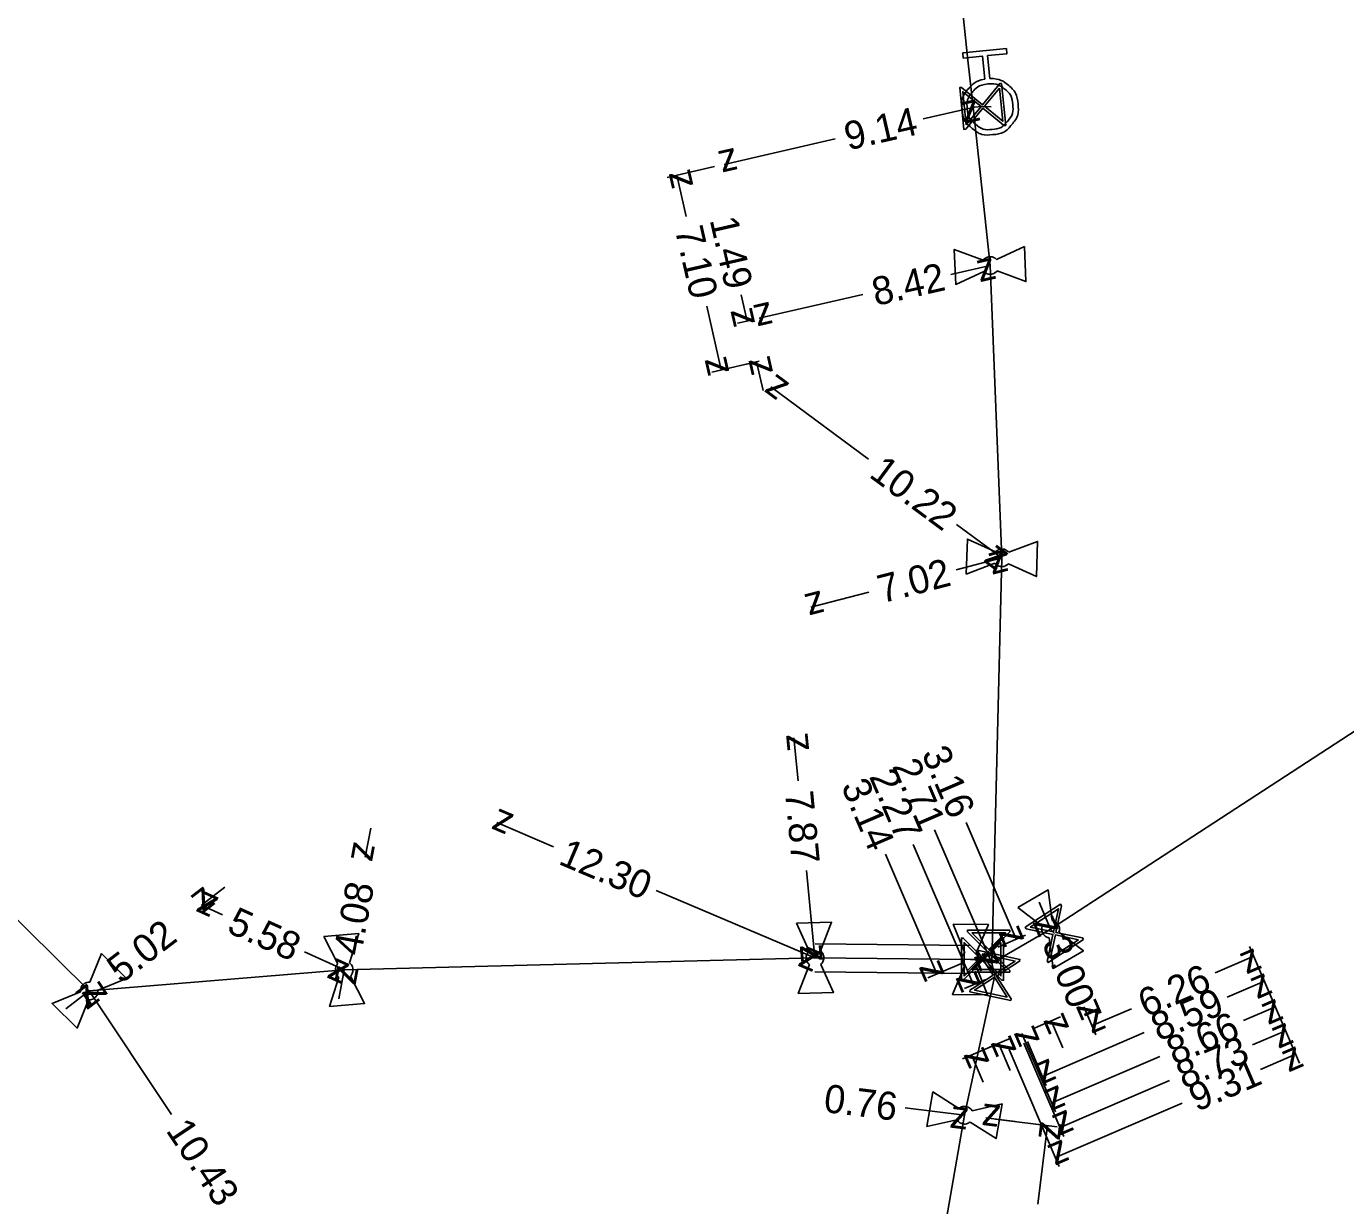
# Model space of a CAD drawing. Extents: x -638315 to -636370, y -1116147 to -1115110.
# Drawn here: x -637124.46 to -637077.52, y -1116031.12 to -1115989.16 of the extents above; entities that cross this region are included whole.
import ezdxf

# ---------------------------------------------------------------- set-up
doc = ezdxf.new("R2010")
doc.units = 0
for name, color, linetype in [('Default', 7, 'Continuous'), ('VP Chránička', 7, 'Continuous'), ('VP Hydrant', 7, 'Continuous'), ('VP Kótování', 7, 'Continuous'), ('VP Lomový bod', 7, 'Continuous'), ('VP Přípojka', 7, 'Continuous'), ('VP Řad', 7, 'Continuous'), ('VP Šoupě', 7, 'Continuous')]:
    doc.layers.add(name, color=color, linetype=linetype)

msp = doc.modelspace()

# ---------------------------------------------------------------- linework, layer by layer
at = {"layer": 'Default'}
for points in [[(-637090.177, -1115991.019), (-637089.816, -1115991.013), (-637089.534, -1115991.246), (-637089.216, -1115991.509), (-637089.174, -1115991.923), (-637089.134, -1115992.335), (-637089.396, -1115992.654), (-637089.659, -1115992.974), (-637090.073, -1115993.015), (-637090.483, -1115993.056), (-637090.803, -1115992.794), (-637091.124, -1115992.532), (-637091.165, -1115992.12), (-637091.206, -1115991.706), (-637090.945, -1115991.386), (-637090.714, -1115991.1), (-637090.359, -1115991.037)], [(-637090.252, -1115991.209), (-637090.588, -1115991.243), (-637090.801, -1115991.502), (-637091.014, -1115991.762), (-637090.98, -1115992.098), (-637090.947, -1115992.434), (-637090.687, -1115992.647), (-637090.428, -1115992.86), (-637090.092, -1115992.826), (-637089.757, -1115992.793), (-637089.544, -1115992.534), (-637089.33, -1115992.274), (-637089.363, -1115991.938), (-637089.397, -1115991.601), (-637089.656, -1115991.389), (-637089.916, -1115991.176), (-637090.252, -1115991.209)], [(-637090.414, -1115997.475), (-637090.382, -1115997.434), (-637090.335, -1115997.405), (-637090.264, -1115997.361), (-637090.182, -1115997.357), (-637090.1, -1115997.354), (-637090.023, -1115997.394), (-637089.976, -1115997.417), (-637089.94, -1115997.456)], [(-637089.923, -1115997.865), (-637089.956, -1115997.905), (-637090.001, -1115997.934), (-637090.075, -1115997.978), (-637090.157, -1115997.982), (-637090.239, -1115997.985), (-637090.314, -1115997.947), (-637090.362, -1115997.922), (-637090.398, -1115997.883)], [(-637089.981, -1116007.857), (-637089.946, -1116007.819), (-637089.899, -1116007.794), (-637089.822, -1116007.755), (-637089.74, -1116007.757), (-637089.658, -1116007.76), (-637089.586, -1116007.804), (-637089.54, -1116007.833), (-637089.507, -1116007.874)], [(-637089.52, -1116008.281), (-637089.556, -1116008.321), (-637089.604, -1116008.346), (-637089.679, -1116008.385), (-637089.761, -1116008.382), (-637089.843, -1116008.379), (-637089.917, -1116008.334), (-637089.962, -1116008.307), (-637089.995, -1116008.265)], [(-637088.073, -1116021.589), (-637088.125, -1116021.579), (-637088.172, -1116021.552), (-637088.245, -1116021.509), (-637088.286, -1116021.438), (-637088.327, -1116021.368), (-637088.328, -1116021.281), (-637088.329, -1116021.228), (-637088.311, -1116021.178)], [(-637087.957, -1116020.973), (-637087.906, -1116020.983), (-637087.86, -1116021.01), (-637087.786, -1116021.054), (-637087.745, -1116021.125), (-637087.704, -1116021.196), (-637087.703, -1116021.28), (-637087.702, -1116021.335), (-637087.72, -1116021.384)], [(-637096.598, -1116022.542), (-637096.639, -1116022.509), (-637096.667, -1116022.462), (-637096.711, -1116022.39), (-637096.713, -1116022.308), (-637096.715, -1116022.227), (-637096.674, -1116022.15), (-637096.65, -1116022.103), (-637096.61, -1116022.068)], [(-637096.202, -1116022.057), (-637096.162, -1116022.09), (-637096.134, -1116022.136), (-637096.09, -1116022.211), (-637096.088, -1116022.292), (-637096.086, -1116022.374), (-637096.126, -1116022.448), (-637096.151, -1116022.497), (-637096.191, -1116022.532)], [(-637091.076, -1116022.594), (-637091.116, -1116022.56), (-637091.142, -1116022.512), (-637091.183, -1116022.438), (-637091.182, -1116022.356), (-637091.181, -1116022.274), (-637091.138, -1116022.199), (-637091.111, -1116022.153), (-637091.071, -1116022.119)], [(-637090.662, -1116022.124), (-637090.623, -1116022.158), (-637090.597, -1116022.205), (-637090.556, -1116022.281), (-637090.557, -1116022.363), (-637090.558, -1116022.445), (-637090.6, -1116022.518), (-637090.628, -1116022.565), (-637090.668, -1116022.599)], [(-637113.334, -1116022.983), (-637113.377, -1116022.952), (-637113.408, -1116022.907), (-637113.455, -1116022.838), (-637113.462, -1116022.756), (-637113.468, -1116022.674), (-637113.432, -1116022.596), (-637113.41, -1116022.547), (-637113.373, -1116022.51)], [(-637112.966, -1116022.476), (-637112.924, -1116022.507), (-637112.893, -1116022.551), (-637112.846, -1116022.623), (-637112.839, -1116022.704), (-637112.832, -1116022.786), (-637112.867, -1116022.862), (-637112.89, -1116022.912), (-637112.928, -1116022.949)], [(-637122.532, -1116023.505), (-637122.536, -1116023.452), (-637122.522, -1116023.399), (-637122.5, -1116023.318), (-637122.443, -1116023.26), (-637122.385, -1116023.202), (-637122.301, -1116023.178), (-637122.251, -1116023.163), (-637122.198, -1116023.167)], [(-637121.907, -1116023.454), (-637121.903, -1116023.506), (-637121.917, -1116023.558), (-637121.941, -1116023.641), (-637121.998, -1116023.699), (-637122.055, -1116023.757), (-637122.136, -1116023.78), (-637122.189, -1116023.795), (-637122.242, -1116023.791)], [(-637091.279, -1116027.657), (-637091.239, -1116027.624), (-637091.188, -1116027.606), (-637091.107, -1116027.578), (-637091.026, -1116027.592), (-637090.946, -1116027.606), (-637090.881, -1116027.66), (-637090.838, -1116027.694), (-637090.812, -1116027.74)], [(-637090.882, -1116028.142), (-637090.923, -1116028.175), (-637090.974, -1116028.194), (-637091.054, -1116028.222), (-637091.134, -1116028.208), (-637091.215, -1116028.193), (-637091.282, -1116028.138), (-637091.323, -1116028.105), (-637091.35, -1116028.059)]]:
    msp.add_open_spline(points, degree=3, dxfattribs=at)
at = {"layer": 'VP Chránička'}
for points in [[(-637090.864, -1116021.86), (-637096.394, -1116021.8)], [(-637090.875, -1116022.859), (-637096.405, -1116022.799)]]:
    msp.add_lwpolyline(points, dxfattribs=at)
at = {"layer": 'VP Hydrant'}
msp.add_lwpolyline([(-637090.359, -1115991.037), (-637090.44, -1115990.221), (-637091.127, -1115990.289), (-637091.145, -1115990.107), (-637089.59, -1115989.952), (-637089.572, -1115990.135), (-637090.258, -1115990.203), (-637090.177, -1115991.019)], dxfattribs=at)
at = {"layer": 'VP Kótování'}
for points in [[(-637092.549, -1115992.453), (-637090.729, -1115992.037)], [(-637095.676, -1115993.169), (-637099.634, -1115994.074)], [(-637099.975, -1115994.152), (-637101.659, -1115994.537)], [(-637100.981, -1115995.93), (-637101.318, -1115994.459)], [(-637091.565, -1115997.989), (-637090.17, -1115997.67)], [(-637099.026, -1115998.719), (-637098.814, -1115999.647)], [(-637094.692, -1115998.704), (-637098.382, -1115999.548)], [(-637100.253, -1115999.112), (-637099.734, -1116001.385)], [(-637098.723, -1115999.626), (-637099.155, -1115999.725)], [(-637098.391, -1116001.078), (-637100.075, -1116001.463)], [(-637098.391, -1116001.078), (-637098.823, -1116001.177)], [(-637098.248, -1116002.122), (-637098.482, -1116001.099)], [(-637094.501, -1116004.556), (-637097.97, -1116001.99)], [(-637091.359, -1116006.88), (-637089.75, -1116008.07)], [(-637091.378, -1116008.491), (-637089.75, -1116008.07)], [(-637094.484, -1116009.295), (-637096.55, -1116009.83)], [(-637097.003, -1116016.005), (-637097.15, -1116014.47)], [(-637105.697, -1116018.35), (-637107.72, -1116017.49)], [(-637091.02, -1116017.484), (-637089.237, -1116021.638)], [(-637112.207, -1116017.688), (-637112.4, -1116018.72)], [(-637092.151, -1116017.742), (-637090.11, -1116022.496)], [(-637093.894, -1116018.616), (-637092.065, -1116022.873)], [(-637092.901, -1116018.272), (-637090.76, -1116023.258)], [(-637096.697, -1116019.199), (-637096.4, -1116022.3)], [(-637117.396, -1116019.792), (-637118.23, -1116020.43)], [(-637102.048, -1116019.9), (-637096.4, -1116022.3)], [(-637117.483, -1116020.768), (-637118.23, -1116020.43)], [(-637088.429, -1116020.317), (-637088.015, -1116021.282)], [(-637089.898, -1116021.922), (-637088.915, -1116021.5)], [(-637080.942, -1116021.892), (-637079.88, -1116024.364)], [(-637080.942, -1116021.892), (-637079.156, -1116026.05)], [(-637080.942, -1116021.892), (-637080.653, -1116022.565)], [(-637080.942, -1116021.892), (-637079.516, -1116025.213)], [(-637080.942, -1116021.892), (-637080.274, -1116023.448)], [(-637114.56, -1116022.092), (-637113.15, -1116022.73)], [(-637082.166, -1116022.834), (-637080.791, -1116022.244)], [(-637113.343, -1116023.762), (-637113.15, -1116022.73)], [(-637091.192, -1116022.498), (-637092.387, -1116023.012)], [(-637090.323, -1116023.07), (-637091.082, -1116023.396)], [(-637081.737, -1116023.696), (-637080.412, -1116023.127)], [(-637123.054, -1116024.118), (-637122.22, -1116023.48)], [(-637119.294, -1116027.875), (-637122.22, -1116023.48)], [(-637086.417, -1116025.004), (-637086.831, -1116024.039)], [(-637085.144, -1116024.112), (-637086.542, -1116024.713)], [(-637081.154, -1116024.53), (-637080.018, -1116024.043)], [(-637088.653, -1116024.822), (-637087.67, -1116024.4)], [(-637087.578, -1116025.503), (-637087.992, -1116024.538)], [(-637086.693, -1116024.361), (-637086.404, -1116025.034)], [(-637089.428, -1116025.154), (-637090.187, -1116025.48)], [(-637088.626, -1116025.953), (-637089.04, -1116024.988)], [(-637084.685, -1116024.961), (-637088.307, -1116026.517)], [(-637080.838, -1116025.4), (-637079.654, -1116024.892)], [(-637089.954, -1116025.38), (-637091.149, -1116025.894)], [(-637089.451, -1116026.307), (-637089.865, -1116025.342)], [(-637089.494, -1116025.564), (-637087.708, -1116029.722)], [(-637088.968, -1116025.338), (-637087.542, -1116028.659)], [(-637088.902, -1116025.31), (-637087.84, -1116027.782)], [(-637088.837, -1116025.282), (-637088.169, -1116026.838)], [(-637090.413, -1116026.72), (-637090.827, -1116025.755)], [(-637084.132, -1116025.809), (-637087.978, -1116027.461)], [(-637080.551, -1116026.269), (-637079.294, -1116025.729)], [(-637083.786, -1116026.666), (-637087.68, -1116028.338)], [(-637083.339, -1116027.465), (-637087.846, -1116029.401)], [(-637093.19, -1116027.639), (-637091.08, -1116027.9)], [(-637089.279, -1116028.123), (-637090.321, -1116027.994)], [(-637089.974, -1116028.037), (-637087.782, -1116028.308)], [(-637088.476, -1116031.06), (-637088.13, -1116028.265)]]:
    msp.add_lwpolyline(points, dxfattribs=at)
at = {"layer": 'VP Lomový bod'}
for points in [[(-637089.94, -1115997.456), (-637088.946, -1115996.995)], [(-637088.946, -1115996.995), (-637088.895, -1115998.244), (-637089.923, -1115997.865)], [(-637090.398, -1115997.883), (-637091.393, -1115998.344), (-637091.444, -1115997.095), (-637090.414, -1115997.475)], [(-637091.021, -1116008.652), (-637090.979, -1116007.403), (-637089.981, -1116007.857)], [(-637089.507, -1116007.874), (-637088.48, -1116007.487), (-637088.522, -1116008.736), (-637089.52, -1116008.281)], [(-637089.995, -1116008.265), (-637091.021, -1116008.652)], [(-637089.183, -1116020.514), (-637088.101, -1116019.887), (-637087.957, -1116020.973)], [(-637088.311, -1116021.178), (-637089.183, -1116020.514)], [(-637113.876, -1116021.536), (-637112.63, -1116021.433), (-637112.966, -1116022.476)], [(-637097.057, -1116021.067), (-637095.808, -1116021.035), (-637096.202, -1116022.057)], [(-637096.61, -1116022.068), (-637097.057, -1116021.067)], [(-637091.481, -1116021.103), (-637090.231, -1116021.116), (-637090.662, -1116022.124)], [(-637091.071, -1116022.119), (-637091.481, -1116021.103)], [(-637087.72, -1116021.384), (-637086.848, -1116022.05), (-637087.929, -1116022.677), (-637088.073, -1116021.589)], [(-637113.373, -1116022.51), (-637113.876, -1116021.536)], [(-637122.198, -1116023.167), (-637121.786, -1116022.151)], [(-637121.786, -1116022.151), (-637120.897, -1116023.03), (-637121.907, -1116023.454)], [(-637096.191, -1116022.532), (-637095.744, -1116023.534), (-637096.993, -1116023.566), (-637096.598, -1116022.542)], [(-637090.668, -1116022.599), (-637090.258, -1116023.616), (-637091.508, -1116023.603), (-637091.076, -1116022.594)], [(-637112.928, -1116022.949), (-637112.424, -1116023.924), (-637113.67, -1116024.027), (-637113.334, -1116022.983)], [(-637122.242, -1116023.791), (-637122.654, -1116024.808), (-637123.543, -1116023.929), (-637122.532, -1116023.505)], [(-637092.419, -1116028.299), (-637092.203, -1116027.068), (-637091.279, -1116027.657)], [(-637090.812, -1116027.74), (-637089.741, -1116027.5), (-637089.957, -1116028.731), (-637090.882, -1116028.142)], [(-637091.35, -1116028.059), (-637092.419, -1116028.299)]]:
    msp.add_lwpolyline(points, dxfattribs=at)
at = {"layer": 'VP Přípojka'}
for points in [[(-637090.777, -1115992.041), (-637090.43, -1115992.01), (-637090.13, -1115992.022)], [(-637087.88, -1116021.43), (-637088.015, -1116021.282)]]:
    msp.add_lwpolyline(points, dxfattribs=at)
at = {"layer": 'VP Řad'}
for points in [[(-637090.11, -1116022.496), (-637088.015, -1116021.282), (-637068.04, -1116008.27), (-637063.353, -1116003.45), (-637050.99, -1115988.7), (-637046.76, -1115976.44), (-637033.727, -1115955.44), (-637030.28, -1115950.07), (-637025.95, -1115945.9), (-637023.92, -1115939.39), (-637022.71, -1115934.13), (-637020.86, -1115927.49), (-637020.52, -1115917.93), (-637020.76, -1115906.31), (-637020.58, -1115902.93), (-637021.02, -1115901.01)], [(-637094.23, -1115955.262), (-637094.039, -1115961.379), (-637092.99, -1115971.5), (-637091.614, -1115983.43), (-637091.423, -1115985.63), (-637091.203, -1115988.085), (-637090.958, -1115990.36), (-637090.777, -1115992.041), (-637090.17, -1115997.67), (-637089.75, -1116008.07), (-637090.11, -1116022.496)], [(-637174.427, -1115967.22), (-637166.44, -1115972.16), (-637160.549, -1115976.135), (-637157.007, -1115978.525), (-637156.97, -1115978.55), (-637144.21, -1115987.34), (-637141.48, -1115990.1), (-637139.35, -1115993.63), (-637138.6, -1115995.44), (-637134.36, -1116007.43), (-637131.69, -1116013.18), (-637129.01, -1116016.77), (-637122.22, -1116023.48), (-637113.15, -1116022.73), (-637096.4, -1116022.3), (-637090.87, -1116022.36), (-637090.44, -1116022.36), (-637090.398, -1116022.36), (-637090.11, -1116022.496)], [(-637092.034, -1116033.336), (-637091.08, -1116027.9), (-637090.001, -1116022.932), (-637090.11, -1116022.496)]]:
    msp.add_lwpolyline(points, dxfattribs=at)
at = {"layer": 'VP Šoupě'}
for points in [[(-637089.758, -1115991.191), (-637089.61, -1115992.684), (-637089.676, -1115992.69), (-637089.773, -1115992.606), (-637090.423, -1115992.074), (-637091.037, -1115992.825), (-637091.103, -1115992.832), (-637091.251, -1115991.339), (-637091.186, -1115991.333), (-637090.435, -1115991.95), (-637089.904, -1115991.3), (-637089.824, -1115991.198), (-637089.758, -1115991.191)], [(-637089.836, -1115991.357), (-637090.367, -1115992.006), (-637089.719, -1115992.536), (-637089.836, -1115991.357)], [(-637091.025, -1115992.671), (-637090.491, -1115992.018), (-637091.142, -1115991.486), (-637091.025, -1115992.671)], [(-637086.842, -1116021.649), (-637088.099, -1116022.468), (-637088.135, -1116022.413), (-637088.105, -1116022.288), (-637087.932, -1116021.466), (-637088.882, -1116021.266), (-637088.918, -1116021.211), (-637087.661, -1116020.392), (-637087.625, -1116020.448), (-637087.828, -1116021.398), (-637087.006, -1116021.57), (-637086.878, -1116021.594), (-637086.842, -1116021.649)], [(-637088.739, -1116021.206), (-637087.914, -1116021.38), (-637087.741, -1116020.556), (-637088.739, -1116021.206)], [(-637089.468, -1116022.813), (-637090.968, -1116022.813), (-637090.968, -1116022.747), (-637090.874, -1116022.659), (-637090.281, -1116022.064), (-637090.968, -1116021.379), (-637090.968, -1116021.313), (-637089.468, -1116021.313), (-637089.468, -1116021.379), (-637090.156, -1116022.064), (-637089.562, -1116022.658), (-637089.468, -1116022.747), (-637089.468, -1116022.813)], [(-637090.816, -1116021.407), (-637090.219, -1116022.002), (-637089.625, -1116021.407), (-637090.816, -1116021.407)], [(-637089.69, -1116021.6), (-637089.69, -1116023.1), (-637089.756, -1116023.1), (-637089.844, -1116023.006), (-637090.439, -1116022.413), (-637091.124, -1116023.1), (-637091.19, -1116023.1), (-637091.19, -1116021.6), (-637091.124, -1116021.6), (-637090.439, -1116022.288), (-637089.845, -1116021.694), (-637089.756, -1116021.6), (-637089.69, -1116021.6)], [(-637091.096, -1116022.948), (-637090.501, -1116022.351), (-637091.096, -1116021.757), (-637091.096, -1116022.948)], [(-637089.784, -1116021.757), (-637090.376, -1116022.351), (-637089.784, -1116022.942), (-637089.784, -1116021.757)], [(-637087.026, -1116021.657), (-637087.846, -1116021.484), (-637088.018, -1116022.303), (-637087.026, -1116021.657)], [(-637089.428, -1116023.824), (-637090.893, -1116023.506), (-637090.879, -1116023.441), (-637090.769, -1116023.375), (-637090.063, -1116022.92), (-637090.589, -1116022.104), (-637090.575, -1116022.04), (-637089.109, -1116022.358), (-637089.123, -1116022.423), (-637089.941, -1116022.947), (-637089.486, -1116023.653), (-637089.414, -1116023.76), (-637089.428, -1116023.824)], [(-637089.625, -1116022.719), (-637090.219, -1116022.127), (-637090.81, -1116022.719), (-637089.625, -1116022.719)], [(-637090.446, -1116022.164), (-637089.989, -1116022.873), (-637089.282, -1116022.417), (-637090.446, -1116022.164)], [(-637089.562, -1116023.699), (-637090.016, -1116022.994), (-637090.719, -1116023.448), (-637089.562, -1116023.699)]]:
    msp.add_lwpolyline(points, dxfattribs=at)

# ---------------------------------------------------------------- texts
at = {"layer": 'VP Kótování'}
for s, rotation, p in [('z', 12.8846, (-637091.105, -1115992.636)), ('9.14', 12.8846, (-637095.224, -1115993.578)), ('z', 192.8846, (-637099.258, -1115993.475)), ('z', 102.8822, (-637100.719, -1115994.835)), ('1.49', 282.8793, (-637100.15, -1115996.044)), ('7.10', 282.8822, (-637101.391, -1115996.383)), ('z', 12.8815, (-637090.546, -1115998.269)), ('8.42', 12.8815, (-637094.24, -1115999.114)), ('z', 282.8793, (-637099.413, -1115999.271)), ('z', 192.8814, (-637098.006, -1115998.949)), ('z', 282.8822, (-637100.332, -1116001.009)), ('z', 102.8793, (-637097.883, -1116001.475)), ('z', 143.5111, (-637097.271, -1116001.885)), ('10.22', 323.5112, (-637094.517, -1116005.166)), ('z', 323.5112, (-637090.449, -1116008.175)), ('z', 14.5111, (-637090.109, -1116008.679)), ('7.02', 14.5111, (-637094.02, -1116009.692)), ('z', 194.5111, (-637096.191, -1116009.221)), ('z', 95.4714, (-637096.605, -1116014.92)), ('3.16', 293.2344, (-637092.62, -1116015.025)), ('2.71', 293.2375, (-637093.669, -1116015.473)), ('2.27', 293.2417, (-637094.488, -1116015.843)), ('3.14', 293.2466, (-637095.482, -1116016.187)), ('7.87', 275.4714, (-637097.467, -1116016.402)), ('z', 156.9788, (-637107.064, -1116017.225)), ('z', 259.4062, (-637112.8, -1116018.137)), ('12.30', 336.9788, (-637105.57, -1116018.947)), ('z', 217.3947, (-637118.136, -1116019.729)), ('z', 155.6411, (-637117.568, -1116020.181)), ('4.08', 79.4062, (-637112.554, -1116022.262)), ('5.58', 335.6411, (-637117.37, -1116021.368)), ('z', 293.2412, (-637088.672, -1116021.02)), ('5.02', 37.3947, (-637121.092, -1116023.247)), ('z', 293.2344, (-637089.893, -1116021.376)), ('z', 336.9788, (-637097.056, -1116022.565)), ('z', 275.4714, (-637096.945, -1116021.85)), ('3.00', 293.2412, (-637088.341, -1116021.79)), ('z', 335.6411, (-637113.812, -1116022.979)), ('z', 293.2466, (-637092.722, -1116022.611)), ('z', 293.2374, (-637090.767, -1116022.234)), ('z', 23.2346, (-637081.053, -1116022.9)), ('z', 79.4062, (-637112.75, -1116023.313)), ('z', 293.2417, (-637091.417, -1116022.996)), ('6.26', 23.2346, (-637084.625, -1116024.434)), ('z', 23.238, (-637080.674, -1116023.783)), ('z', 37.3947, (-637122.314, -1116024.181)), ('z', 123.6596, (-637121.527, -1116023.619)), ('z', 113.2412, (-637086.174, -1116024.301)), ('8.59', 23.238, (-637084.166, -1116025.283)), ('z', 23.2385, (-637080.28, -1116024.699)), ('z', 113.2343, (-637087.335, -1116024.8)), ('z', 203.2347, (-637086.28, -1116024.056)), ('8.66', 23.2385, (-637083.613, -1116026.131)), ('z', 113.2374, (-637088.383, -1116025.25)), ('z', 23.2365, (-637079.916, -1116025.548)), ('z', 113.2417, (-637089.208, -1116025.604)), ('8.73', 23.2365, (-637083.267, -1116026.987)), ('z', 113.2465, (-637090.171, -1116026.018)), ('z', 23.2374, (-637079.556, -1116026.386)), ('z', 203.238, (-637088.044, -1116025.86)), ('9.31', 23.2374, (-637082.82, -1116027.787)), ('0.76', 352.9401, (-637096.12, -1116027.78)), ('z', 203.2385, (-637087.716, -1116026.804)), ('z', 172.94, (-637089.763, -1116027.559)), ('z', 352.94, (-637091.638, -1116028.335)), ('z', 203.2365, (-637087.418, -1116027.681)), ('10.43', 303.6596, (-637119.516, -1116028.443)), ('z', 82.9476, (-637087.695, -1116028.823)), ('z', 203.2374, (-637087.584, -1116028.744))]:
    msp.add_text(s, height=1, rotation=rotation, dxfattribs=at).set_placement(p)

doc.saveas('drawing.dxf')
